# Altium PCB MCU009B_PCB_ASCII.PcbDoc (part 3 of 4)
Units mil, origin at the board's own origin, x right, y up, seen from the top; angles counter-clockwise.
Board outline 2657.23 x 2215.46 mil, 10 copper layers (Top Layer, Internal-Plane 2, Mid-Layer 3, Mid-Layer 4, Internal-Plane 5, Internal-Plane 6, Mid-Layer 7, Mid-Layer 8, Internal-Plane 9, Bottom Layer), stack 60.8 mil thick; 232 components, 196 nets, 851 pads, 493 vias.
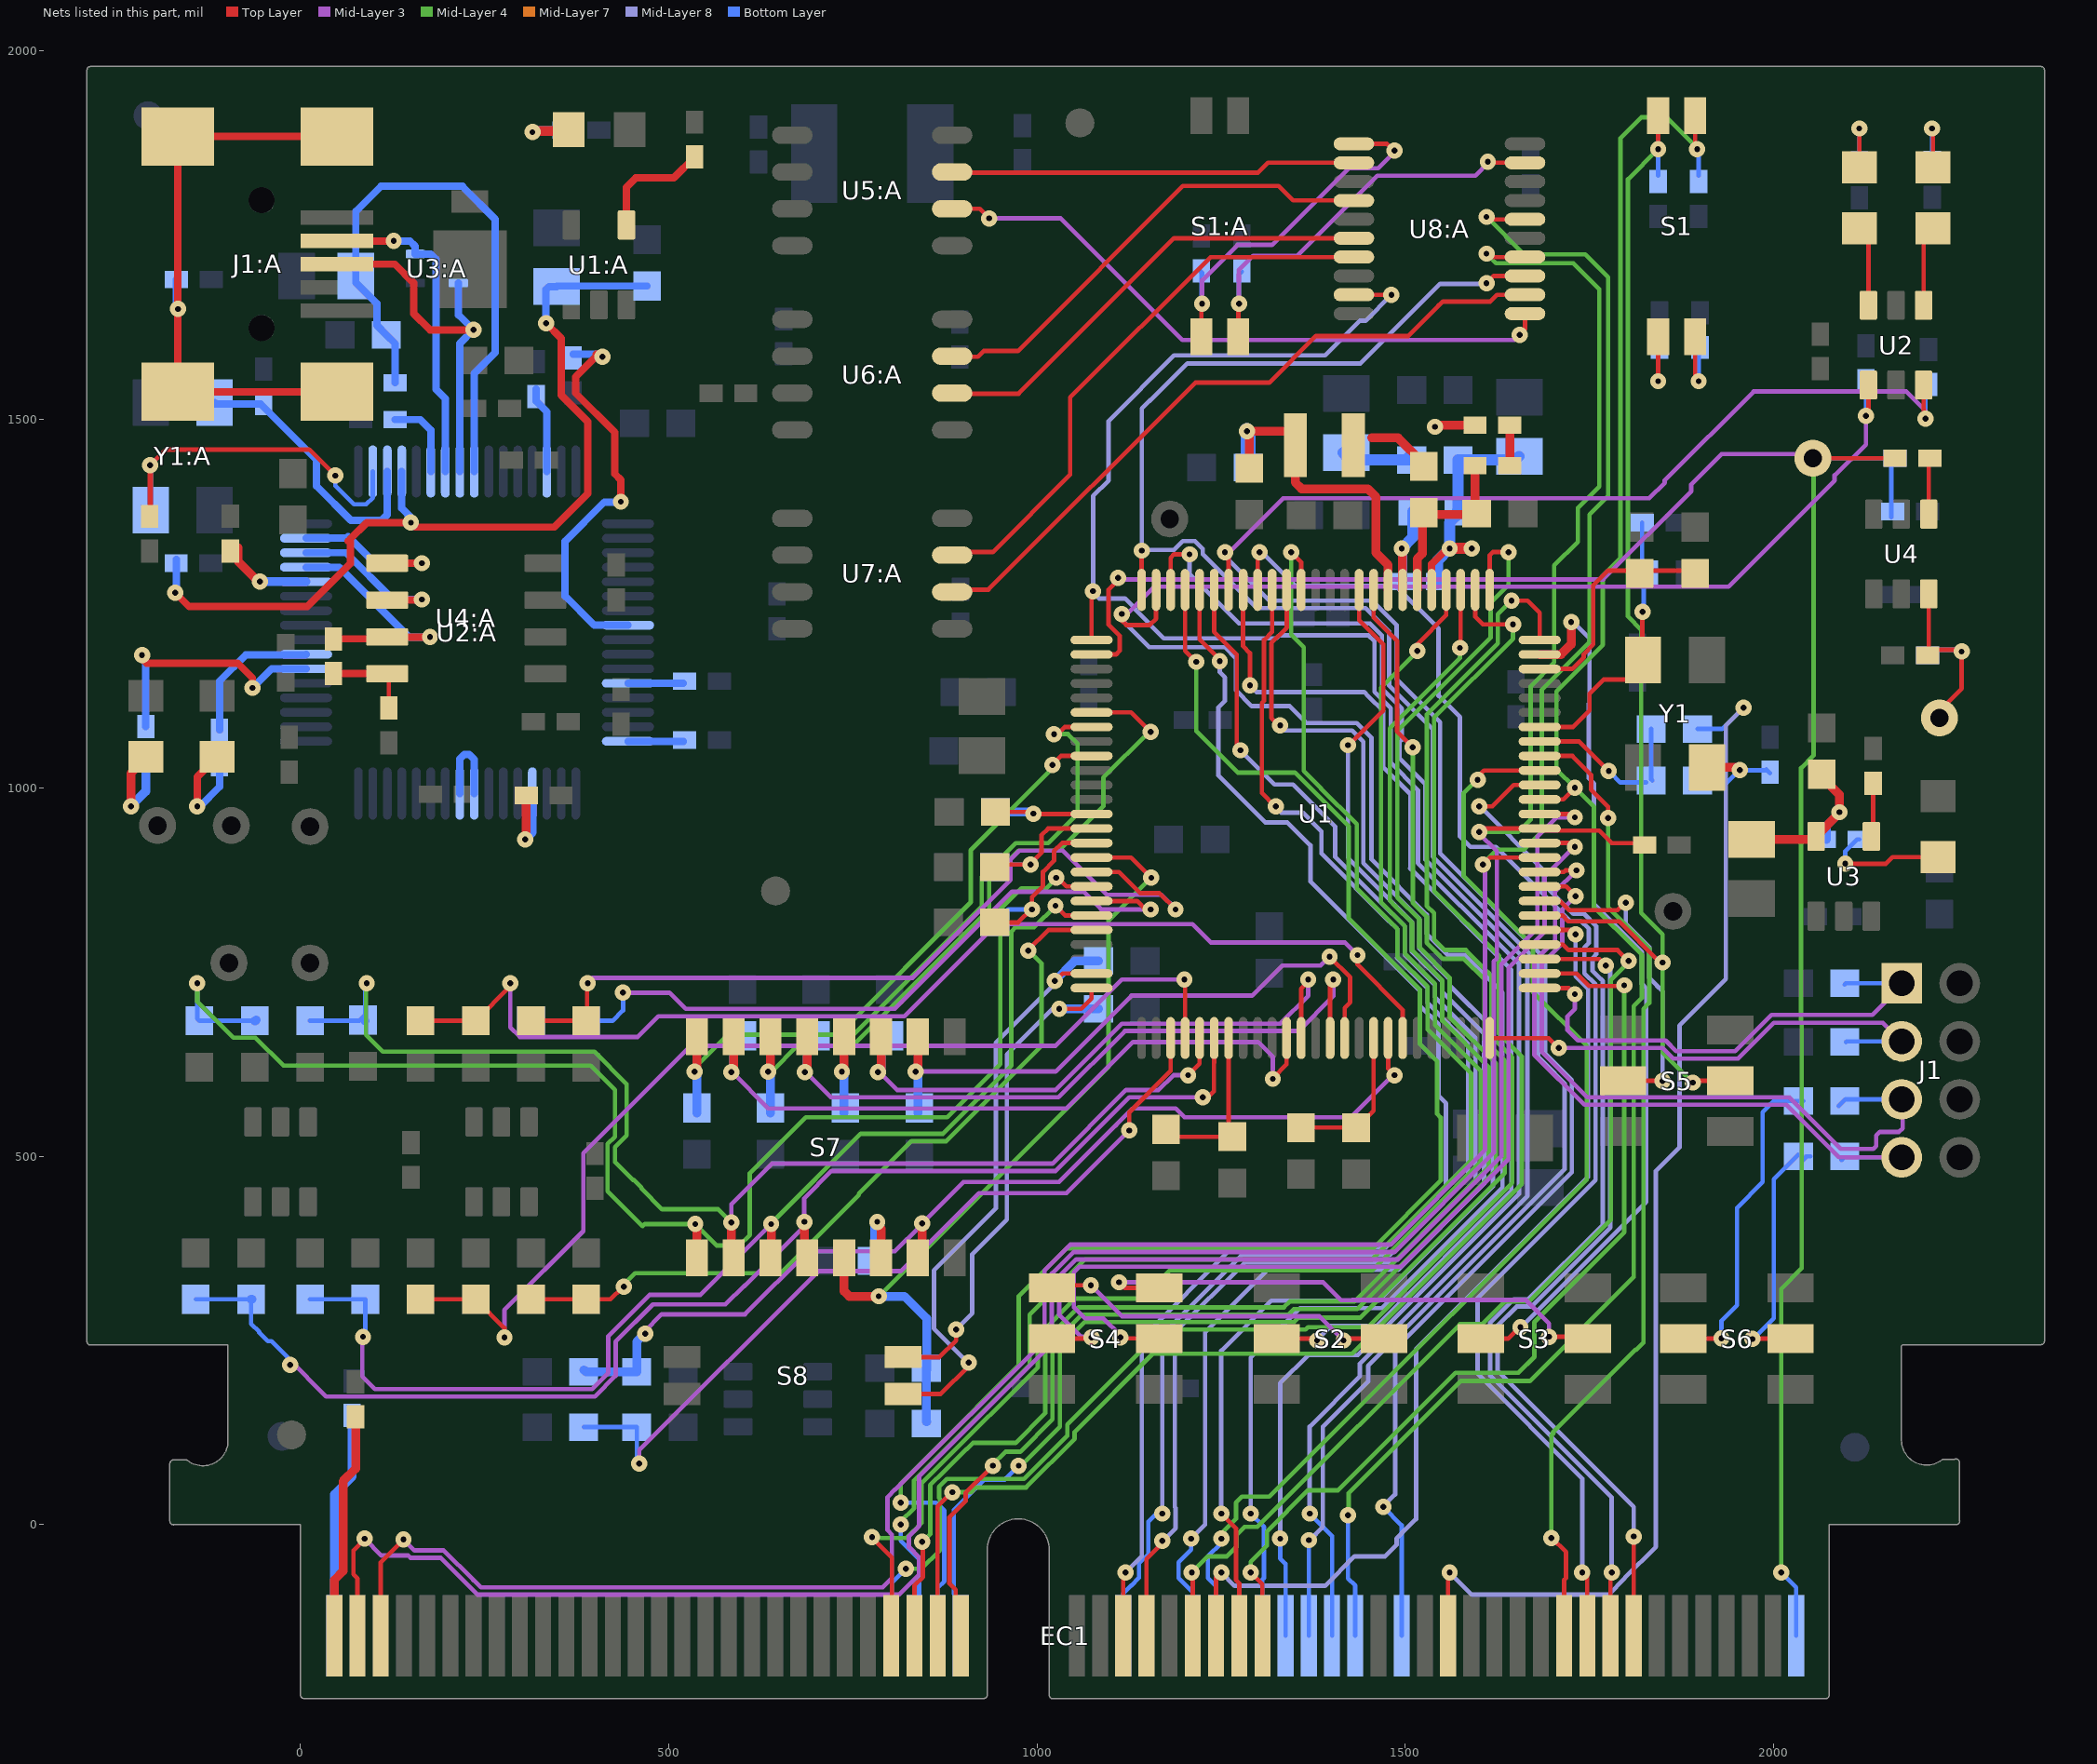
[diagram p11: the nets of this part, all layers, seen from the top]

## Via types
v1: diameter 22, hole 8, Top Layer to Bottom Layer, 414 vias
v2: diameter 22, hole 8, Top Layer to Bottom Layer, tented both sides, 79 vias

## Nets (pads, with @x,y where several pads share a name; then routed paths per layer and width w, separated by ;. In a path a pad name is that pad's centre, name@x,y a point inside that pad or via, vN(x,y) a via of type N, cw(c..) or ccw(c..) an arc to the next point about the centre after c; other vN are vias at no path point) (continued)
MCU_ADC-C0: C55.1 R60.1 U1.19 | length 1040.5
  Top Layer w6: U1.19@1073.97,846.45 1135.55,846.45 v1@1149,833
  Mid-Layer 3 w6: v1(438,722) v1@439,722 ; v1@438,723 v1@439,722 ; v1(1154,835) 1087,835 1063,859 966,859 807,700 523,700 501,722 v1@439,722
  Bottom Layer w6: R60.1@313.1,683.9 C55.1@390.9,683.9 ; C55.1@388.1,683.9 C55.1@390.89,683.9 ; v1(438,722) 438,698 423.9,683.9 C55.1@390.89,683.9
MCU_ADC-C1: C56.1 R61.1 U1.29 | length 1432.9
  Top Layer w6: C56.1@163.1,305.9 R61.1@237.9,305.9 ; R61.1@238.1,305.9 277,267 v1(277,254) v1@277,252 ; v1(1200,740) 1200.93,739.07 U1.29@1200.93,660.43
  Mid-Layer 3 w6: v1(277,254) 277,291.46 384,398.46 384,504 530,650 1025,650 1115,740 v1(1200,740)
MCU_ADC-C2: C57.1 R62.1 U1.21 | length 1073.7
  Top Layer w6: R62.1@313.1,305.9 C57.1@390.9,305.9 ; C57.1@388.1,305.9 420.9,305.9 v1@437,322 ; v1@987.5,779.5 1015.08,807.08 U1.21@1073.97,807.08
  Mid-Layer 4 w6: v1@437,324 454.27,341.27 651.73,341.27 758,447.54 758,449 829.5,520.5 876.64,520.5 1006,649.86 1006,762 v1@988,780
  other v1: 439,323 988,779
MCU_ADC-C4: C58.1 R63.1 U1.17 | length 1187.2
  Top Layer w6: R63.1@313.1,683.9 389.1,683.9 389.1,734.1 v1(390,735) ; U1.17@1073.97,885.82 1111.18,885.82 1140,857 1166,857 v1(1188,835)
  Mid-Layer 3 w6: v1@388,735 395,742 831,742 964,875 964,903 976,915 1035,915 1095,855 1169,855 1188,836 v1(1188,835)
MCU_ADC-C14: C59.1 R64.1 U1.44 | length 1585.8
  Top Layer w6: C59.1@163.1,683.9 R64.1@237.9,683.9 ; R64.1@238.1,683.9 285,730.8 v1(285,735) v1@285,740 ; v1(1435,773) 1435,760 1496.21,698.79 U1.44@1496.21,660.43
  Mid-Layer 3 w6: v1(285,735) 285,675 298,662 458,662 486,690 820,690 945,815 1211,815 1236,790 1418,790 v1(1435,773) v1@1436,772
MCU_ADC-PGA1: C41.2 R37.2 S7.1 U1.18 | length 2040.2
  Top Layer w6: v1(1026,878) 1028,878 1039.86,866.14 U1.18@1073.97,866.14
  Top Layer w12: v1(536,408) 538.1,405.9 S7.1@538.1,362.4
  Mid-Layer 4 w6: v1@-140,740 v1(-140,735) -140,710 -91,661 -61,661 -23,623 394,623 427,590 427,526.6 417,516.6 417,452.54 464.54,405 467.54,408 v1(536,408) 565,379 596,379 610,393 610,477 686,553 878,553 950,625 950,835 978.5,863.5 1012.5,863.5 1026,877 v1(1026,878)
  Bottom Layer w6: v1(-140,735) -140,686.99 C41.2@-136.9,683.9 -62.1,683.9 R37.2@-61,685
  Bottom Layer w12: R37.2@-61.9,683.9 -61.1,683.9 R37.2@-60,685
MCU_ADC-PGA1OF: C34.2 S7.16 U1.9 | length 877.1
  Top Layer w6: v1(1021,1031) 1021,1032 1032.3,1043.3 U1.9@1073.97,1043.3
  Top Layer w12: v1(535,615) 538.1,618.1 S7.16@538.1,662.4
  Mid-Layer 4 w6: v1@530,615 580,665 730,665 910,845 910,915.46 1025.54,1031 v1(1021,1031)
  Bottom Layer w12: C34.2@538.1,558.89 C34.2@538.1,565.5 v1@538.1,615
MCU_ADC-PGA2: C42.2 R39.2 S7.2 U1.30 | length 1707.2
  Top Layer w6: v1(1205,610) 1220.62,625.62 U1.30@1220.62,660.43
  Top Layer w12: v1(585,410) 585,365 S7.2@590,360
  Mid-Layer 3 w6: v1(585,410) 585,435 640,490 1020.86,490 1120.86,590 1165,590 1185,610 v1(1205,610)
  Mid-Layer 4 w6: v1@90,736 89,735 89,665 112,642 399,642 443,598 443,528.46 427,512.46 427,492 451,468 452.46,468 463,457.46 463,456 491,428 567,428 v1(585,410)
  Bottom Layer w6: R39.2@13.1,683.9 79.9,683.9 88,692 88,733 v1(90,735)
MCU_ADC-PGA2OF: C35.2 S7.15 U1.36 | length 986.9
  Top Layer w6: v1(1320,605) 1320,606 1338.73,624.73 U1.36@1338.73,660.43
  Top Layer w12: v1(585,614) 588.1,617.1 S7.15@588.1,662.4
  Mid-Layer 3 w6: v1(585,614) 586,614 635,565 1040,565 1130,655 1300,655 1320,635 v1(1320,605)
  Bottom Layer w12: v1(585,614) 588.1,617.1 C35.2@588.1,655.91
MCU_ADC-PGA3: C43.2 R40.2 S7.3 U1.20 | length 1628.3
  Top Layer w6: v1@1027.5,837.5 1038.23,826.77 U1.20@1073.97,826.77
  Top Layer w12: v1@635,408.8 635.8,408 v1(639,408) 639,369 635,365 S7.3@640,365
  Mid-Layer 3 w6: v1@84,257 84,201 101,184 395.86,184 418,206.14 418,255.86 474.14,312 543,312 v1@633,402
  Mid-Layer 4 w6: v1(639,408) 639,409 760.5,530.5 872.5,530.5 965,623 965,805 971,811 996,811 v1(1025,840)
  Bottom Layer w6: R40.2@13.1,305.9 C43.2@87.1,305.9 ; v1@88.1,260.1 C43.2@88.1,305.9
  other v1: 85,255
MCU_ADC-PGA3OF: C36.2 S7.14 U1.7 | length 886.8
  Top Layer w6: v1(1023,1073) 1028,1073 1037.67,1082.67 U1.7@1073.97,1082.67
  Top Layer w12: v1(635,615) 638.1,618.1 S7.14@638.1,662.4
  Mid-Layer 4 w6: v1@630,615 v1(635,615) 640,615 675,650 735.86,650 925,839.14 925,879.14 970.86,925 1015,925 1055,965 1055,1060 1042,1073 v1(1023,1073)
  Bottom Layer w12: v1(635,615) 638.1,611.9 C36.2@638.1,565.5 C36.2@638.1,558.89
MCU_ADC-PGA4: C44.2 R42.2 S7.4 U1.31 | length 1796.4
  Top Layer w6: v1(1225,580) 1232,580 1240,588 1240,626.39 1240.3,626.7 U1.31@1240.3,660.43
  Top Layer w12: v1(684,411) 684,371 S7.4@690,365
  Mid-Layer 3 w6: v1@-16,225 35,174 400,174 428,202 428,248.46 478.54,299 577,299 603,325 ; 602,323 v1@681,402 ; v1(684,411) 684,443 721,480 1025,480 1125,580 v1(1225,580)
  Bottom Layer w6: C44.2@-141.9,305.9 R42.2@-70.9,305.9 ; R42.2@-66.9,305.9 -66.9,272.68 -55.73,261.51 -55.73,260.73 -44,249 -39,249 -14,224 v1(-14,217)
  Bottom Layer w12: R42.2@-66.9,305.9 R42.2@-65.9,305.9
MCU_ADC-PGA4OF: C37.2 S7.13 U1.39 | length 985.9
  Top Layer w6: U1.39@1397.79,660.43 1397.79,737.21 1400.57,740 v1(1402,740)
  Top Layer w12: v1(685,614) 688.1,617.1 S7.13@688.1,662.4
  Mid-Layer 3 w6: v1(685,614) 686,614 720,580 1029.14,580 1119.14,670 1355,670 1402,717 v1(1402,740)
  Bottom Layer w12: v1(685,614) 688.1,617.1 C37.2@688.1,655.91
MCU_ADC-PGA5: C45.2 R43.2 S7.5 U1.16 | length 1131.2
  Top Layer w6: U1.16@1073.97,905.51 1127.49,905.51 v1(1155,878) v1@1156,877
  Top Layer w12: S7.5@738.1,362.4 738.1,316.9 745,310 v1(785,310)
  Mid-Layer 4 w6: v1(785,310) 1097,622 1097,820 v1(1155,878)
  Bottom Layer w12: v1(785,310) 820,310 850,280 R43.2@850,210 ; R43.2@849.6,212.4 849.59,139.59 C45.2@850,140
MCU_ADC-PGA5OF: C38.2 S7.12 U1.6 | length 865.1
  Top Layer w6: U1.6@1073.97,1102.36 1127.64,1102.36 v1(1154,1076) v1@1155,1075
  Top Layer w12: v1(735,615) 738.1,618.1 S7.12@738.1,662.4
  Mid-Layer 4 w6: v1(735,615) 735,635 935,835 935,875 975,915 1030,915 1090,975 1090,1014 1152,1076 v1(1154,1076)
  Bottom Layer w12: C38.2@738.1,558.89 v1@738.1,615
MCU_ADC-PGA6: C46.2 R45.2 U1.28 | length 1131.5
  Top Layer w6: v1(1125,535) 1125,559.54 1181.25,615.79 U1.28@1181.25,660.43
  Mid-Layer 3 w6: v1@460,85 460,101 703,344 815,344 921,450 1040,450 v1(1125,535)
  Bottom Layer w6: C46.2@384.6,132.4 419.6,132.4 ; 420.4,132.4 R45.2@456.6,132.4 456.6,86.4 v1(460,83)
MCU_ADC-PGA6OF: C39.2 S7.11 U1.37 | length 846.9
  Top Layer w6: U1.37@1358.41,660.43 1358.41,727.41 v1@1370,739
  Top Layer w12: v1(784,614) 788.1,618.1 S7.11@788.1,662.4
  Mid-Layer 3 w6: v1(784,614) 785,615 810,590 1025,590 1115,680 1330,680 1368,718 v1(1368,740)
  Bottom Layer w12: v1(784,614) 788.1,618.1 C39.2@788.1,655.91
MCU_ADC-PGA7: C47.2 R46.2 S7.7 U1.43 | length 1402.7
  Top Layer w6: 1476.53,618.47 U1.43@1476.53,660.43
  Top Layer w12: S7.7@838.1,362.4 844,368.3 v1(844,409)
  Mid-Layer 3 w6: v1@467,262 490.5,285.5 603.5,285.5 689,371 807,371 842,406 v1@841,406 ; v1(844,409) v1@841,406 ; v1@1487,614 1426,553 1200,553 1188,565 1129.54,565 1107,542.46 1107,542 1030,465 900,465 v1@841,406
  Bottom Layer w12: C47.2@385,210 387.6,207.4 R46.2@456.6,207.4 456.6,248.4 467.21,259 v1(468,259)
  other v1: 1485,610
MCU_ADC-PGA7OF: C40.2 S7.10 U1.40 | length 856.6
  Top Layer w6: v1@1395,773 v1(1397,771) 1425,743 1425,709 1417.47,701.47 U1.40@1417.47,660.43
  Top Layer w12: v1(835,615) 838.1,618.1 S7.10@838.1,662.4
  Mid-Layer 3 w6: v1(835,615) 1025,615 1128,718 1292,718 1333,759 1385,759 v1@1394,768
  Bottom Layer w12: v1(835,615) 838.1,611.9 C40.2@838.1,558.89
MCU_GPIO-00: EC1.49 U1.79 | length 2109
  Top Layer w6: v1@775,-17 803,-45 803,-149.64 EC1.49@801.97,-150.67 ; v1@1516,1185 v1(1516,1186) 1516,1195 1555.27,1234.27 U1.79@1555.27,1268.7
  Mid-Layer 4 w6: v1@776,-16 778,-18 822.46,-18 831.73,-8.73 ; 832,-9 843,2 843,55.74 869.26,82 ; 869.28,82 1001,213.72 1001,256 1052,307 1142,307 1180,345 1455,345 1602,492 1602,616 1540,678 1540,734.28 1499,775.28 1499,812.6 1467,844.6 1467,1136 v1@1516,1185
  other v1: 776,-17
MCU_GPIO-01: EC1.51 U1.78 | length 2089
  Top Layer w6: EC1.51@833.46,-150.67 833.46,-82.54 845,-71 v1@845,-24 ; v1(1574,1190) 1574.95,1190.95 U1.78@1574.95,1268.7
  Mid-Layer 4 w6: v1@844.5,-23.5 855,-13 855,53.6 873.4,72 ; 873.43,72 903.71,102.29 ; 904,102 913,111 971,111 1011,151 1011,249.74 1056.26,295 1335,295 1343,303 1431,303 1613,485 1613,621 1550,684 1550,738.43 1509,779.43 1509,816.74 1486.74,839 1486.74,839.26 1479,847 1479,1081.14 1574,1176.14 v1(1574,1190) v1@1576,1192
  other v1: 844,-23
MCU_GPIO-02: EC1.53 U1.77 | length 2103
  Top Layer w6: EC1.53@864.96,-150.67 864.96,24.96 v1@885,45 ; U1.77@1594.64,1268.7 1594.64,1232.36 1605,1222 v1(1646,1222) v1@1648,1222
  Mid-Layer 4 w6: v1(885,44) 910,44 916.52,50.52 985.12,50.52 1051,116.4 1051,126 1157,232 1427.46,232 1658,462.54 1658,635.28 1627,666.28 1627,772 1539,860 1539,1095.46 1646,1202.46 v1(1646,1222)
MCU_GPIO-03: EC1.55 U1.76 | length 2166.3
  Top Layer w6: EC1.55@889.32,-116 889.32,-88.32 881,-80 881,10 903,32 903,43 v1(940,80) ; U1.76@1614.32,1268.7 1614.32,1315.68 1618.64,1320 v1(1640,1320)
  Mid-Layer 4 w6: v1@939,81 957,99 977,99 1021,143 1021,245.6 1060.4,285 1341,285 1348.5,292.5 1434.64,292.5 1623,480.86 1623,626 1560,689 1560,742.57 1519,783.57 1519,821.14 1489,851.14 1489,1077 1615.5,1203.5 1615.5,1250.96 1640,1275.46 v1(1640,1320) ; v1(940,80) v1@940,81
MCU_GPIO-04: EC1.50 U1.75 | length 2184.7
  Top Layer w6: v1(1644,1254) 1666,1254 1682.23,1237.77 U1.75@1682.23,1200.78
  Mid-Layer 4 w6: v1(822,-60) 843,-60 868,-35 868,35.54 867,36.54 867,51.46 877.54,62 982.46,62 1041,120.54 1041,136 1170,265 1364.54,265 1367.54,268 1449.31,268 1645,463.69 1645,634.14 1617,662.14 1617,744.6 1612.8,748.8 ; 1613,749 1582,780 1553.14,780 1539,794.14 1539,830 1529,840 1529,1099.6 1625.5,1196.1 1625.5,1235.5 v1(1644,1254)
  Bottom Layer w6: EC1.50@801.97,-150.67 803,-149.64 803,-79 v1(822,-60)
MCU_GPIO-05: EC1.52 U1.89 | length 2190.7
  Top Layer w6: v1(1345,1320) 1358.41,1306.59 U1.89@1358.41,1268.7
  Mid-Layer 4 w6: v1(815,0) 815,4.54 833,22.54 833,59.88 865.12,92 ; 865.14,92 990,216.86 990,285 1065,360 1455,360 1589,494 1589,613 1530,672 1530,730.14 1489,771.14 1489,808.46 1434,863.46 1434,950.6 1385,999.6 1385,1000 1362,1023 1362,1191 1345,1208 v1(1345,1320)
  Bottom Layer w6: v1(815,0) 815,-22 840,-47 840,-144.13 EC1.52@833.46,-150.67
MCU_GPIO-06: EC1.54 U1.97 | length 2213.7
  Top Layer w6: U1.97@1200.93,1268.7 1200.93,1186.07 v1(1216,1171)
  Mid-Layer 4 w6: v1(815,30) 815,56.02 860.98,102 975,216 975,310 1040,375 1455.86,375 1548,467.14 1548,552.46 1543,557.46 1543,629 1519.7,652.3 1519.7,726.3 1464,782 1463.54,782 1423,822.54 1423,947.46 1349.73,1020.73 1272.27,1020.73 1216,1077 v1@1216,1170 ; v1@1215,1171 v1@1216,1170 ; v1(1216,1171) v1@1216,1170
  Bottom Layer w6: v1(815,30) 863,30 874,19 874,-77 864.96,-86.04 EC1.54@864.96,-150.67
MCU_GPIO-07: EC1.56 U1.84 | length 2014.8
  Top Layer w6: U1.84@1456.84,1268.7 1456.84,1231.16 1488.5,1199.5 1488.5,1076.5 v1(1510,1055)
  Mid-Layer 4 w6: v1@976,78 1031,133 1031,241.46 1064.54,275 1349,275 1355,281 1439,281 1635,477 1635,630 1607,658 1607,740.46 1579.46,768 1551,768 1529,790 1529,825.28 1510,844.28 v1(1510,1055)
  Bottom Layer w6: EC1.56@889.32,-111 889.32,-96.32 887,-94 887,20 928,61 956,61 v1(975,80)
MCU_GPIO-08: S3.5 U1.74 | length 1209.5
  Top Layer w6: S3.5@1602.17,252.4 1639.4,252.4 v1@1656,269
  Top Layer w12: U1.74@1682.23,1181.1 1711.1,1181.1 1725,1195 v1(1725,1225)
  Mid-Layer 8 w6: v1(1656,268) 1657,268 1827,438 1827,728 1821,734 1821,777 1756,842 1756,1006 1749,1013 1749,1114.54 1750,1115.54 1750,1203 v1@1728,1225
MCU_GPIO-09: EC1.71 U1.90 | length 1854.2
  Top Layer w6: v1(1250,15) 1270,-5 1270,-75 1274.41,-79.41 EC1.71@1274.41,-150.67 ; v1@1329,1084 1318,1095 1318,1196.46 1339,1217.46 1339,1268.43 U1.90@1338.73,1268.7
  Mid-Layer 8 w6: v1(1250,15) 1250,236 1318,304 1463.86,304 1618.71,458.86 1618.71,673.29 1560,732 1560,740.57 1519,781.57 1519,822 1443,898 1443,1062.46 1427.46,1078 1336,1078 v1@1330,1084
  other v1: 1330,1085
MCU_GPIO-10: S2.2 U1.93 | length 1453.3
  Top Layer w6: U1.93@1279.67,1268.7 1279.67,1192.33 1289,1183 v1@1289,1145 ; S2.2@1325.27,252.4 1377.6,252.4 v1(1380,250)
  Mid-Layer 8 w6: v1(1289,1139) 1298,1130 1444,1130 1450,1124 ; v1(1380,250) 1379,250 1399,270 1461,270 1643.86,452.86 1643.86,753.14 1507,890 ; 1450.07,1124.07 1470,1104.14 1470,1028 1507,991 1507,890 ; 1506,891 1507,890
MCU_GPIO-11: EC1.73 U1.52 | length 1300.4
  Top Layer w6: v1(1290,-65) 1305.9,-80.9 EC1.73@1305.9,-150.67 ; U1.52@1682.23,748.03 1731.97,748.03 1749,731 1798,731 v1@1801,734
  Mid-Layer 4 w6: v1(1290,-65) 1290,-50.46 1312,-28.46 1312,-9 1367.73,46.73 1408.73,46.73 1568,206 1653.46,206 1675,227.54 1675,275 1797,397 v1(1797,732)
MCU_GPIO-12: J1.1 R3.2 U1.51 | length 688.4
  Top Layer w6: U1.51@1682.23,728.34 1721.66,728.34 v1(1730,720)
  Mid-Layer 3 w6: v1(1730,720) 1730,700 1720,690 1720,671 1734,657 1853.14,657 1867.64,642.5 1947.5,642.5 1997,692 2134,692 J1.1@2176,734
  Bottom Layer w6: R3.2@2096,733 2097.75,734.75 J1.1@2173.62,734.75
MCU_GPIO-13: J1.3 R4.2 U1.50 | length 690.4
  Top Layer w6: U1.50@1614.32,660.43 1694.57,660.43 v1(1708,647)
  Mid-Layer 3 w6: v1(1708,647) 1849,647 1863.5,632.5 1951.64,632.5 2000.14,681 2148,681 J1.3@2174,655 ; J1.3@2181.31,663.69 J1.3@2185,660
  Bottom Layer w6: R4.2@2098,655 2099.01,656.01 J1.3@2173.62,656.01 ; J1.3@2180,655 J1.3@2185,660
MCU_GPIO-14: EC1.61 U1.96 | length 1887.7
  Top Layer w6: EC1.61@1116.93,-150.67 1116.93,-66.93 1118.86,-65 v1(1120,-65) ; U1.96@1220.62,1268.7 1220.62,1201.38 v1@1249,1173
  Mid-Layer 8 w6: v1(1120,-65) 1142,-43 1142,253 1265,376 1473,376 1555,458 1555,572 1545,582 1545,678.98 1520,703.98 1520,724 1371,873 1371,922 1340,953 1310,953 1246,1017 1246,1109 1255,1118 1255,1150 1248,1157 v1(1248,1172) ; v1@1248,1174 v1@1249,1173
MCU_GPIO-15: EC1.63 U1.95 | length 1884.9
  Top Layer w6: EC1.63@1148.42,-150.67 1148.42,-46.58 1170,-25 v1(1170,-22) ; U1.95@1240.3,1268.7 1240.3,1211.7 1271,1181 1271,1056 v1(1276,1051)
  Mid-Layer 8 w6: v1@1171,-22 1188,-5 1188,22.46 1187,23.46 1187,260.86 1282.14,356 1484,356 1595,467 1595,661 1540,716 1540,732.28 1499,773.28 1499,812.6 1482.6,829 1482,829 1404.5,906.5 1404.5,947.5 1347.5,1004.5 1322.5,1004.5 v1(1276,1051)
MCU_GPIO-16: EC1.67 U1.54 | length 1358.2
  Top Layer w6: v1(1210,-65) 1211.42,-66.42 EC1.67@1211.42,-150.67 ; U1.54@1682.23,787.4 1714,787.4 1721.4,780 1788,780 v1(1803,765) ; v1@1801,763 v1@1804,760
  Mid-Layer 4 w6: v1(1210,-65) 1232,-43 1257.46,-43 1271,-29.46 1271,-13.54 1281.54,-3 1299,-3 1574,272 1604,272 1635,303 1668,303 1779,414 1779,739.46 1803,763.46 v1(1803,765)
MCU_GPIO-17: EC1.69 U1.55 | length 1352
  Top Layer w6: EC1.69@1242.91,-150.67 1242.91,-72.09 v1(1250,-65) ; U1.55@1682.23,807.08 1723.92,807.08 v1@1731,800
  Mid-Layer 8 w6: v1(1250,-65) 1268,-83 1391,-83 1431,-43 1472.46,-43 1488,-27.46 1488,-19 1514.5,7.5 1514.5,238.33 1748,471.83 1748,727.46 1731,744.46 v1(1731,801)
MCU_GPIO-18: R7.2 R16.2 U1.68 | length 240.8
  Top Layer w6: U1.68@1682.23,1062.99 1736.01,1062.99 v1(1776,1023) v1@1780,1019
  Bottom Layer w6: v1@1778,1021 1791.6,1007.4 R16.2@1826.6,1007.4 ; R7.2@1833.5,1080 1833.5,1011.5 R16.2@1835,1010
MCU_GPIO-22: L3.2 R19.1 R22.2 U1.83 | length 477.7
  Top Layer w12: v1@1286,1484 1353,1484 L3.2@1360,1477 ; R22.2@1288.1,1433.9 v1@1288.1,1481.9 ; L3.2@1350.63,1465 1350.63,1414.37 1359,1406 1449,1406 1460,1395 1460,1319 1476.53,1302.47 U1.83@1476.53,1268.7
  Bottom Layer w20: v1(1285,1484) 1285,1485 1286.5,1483.5 R19.1@1286.5,1435
MCU_GPIO-23: R18.1 R21.2 R24.2 U1.81 | length 253.2
  Top Layer w12: U1.81@1515.9,1268.7 1515.9,1307.1 ; R21.2@1515.9,1365.9 R21.2@1517,1364.79 ; 1516,1307 1515.9,1307.1 ; R21.2@1518,1373 R21.2@1520.1,1370.9 ; R24.2@1594.48,1437.4 R18.1@1594.48,1370.52 ; R18.1@1595,1370 R18.1@1594.48,1370.52 ; 1515.9,1307.1 1515.9,1310.9 1523,1318 1523,1368 R21.2@1520.1,1370.9 ; R21.2@1520.1,1370.9 1594.1,1370.9 R18.1@1594.48,1370.52
MCU_GPIO-24: R25.2 S1.2 S5.2 U1.56 | length 1649.9
  Top Layer w6: U1.56@1680,827 U1.56@1682.23,827 ; U1.56@1682.23,826.77 1713.23,826.77 1721,819 1790,819 v1@1843,766 ; S1.2@1843.1,1912.4 v1@1843.1,1869.1 ; v1(1890,600) 1892.4,602.4 S5.2@1940.93,602.4 ; v1(1843,1867) 1843.1,1866.9 v1@1843.1,1869.1 ; v1(1843,1867) 1842,1868 v1@1843,1869 ; v1(1843,1867) v1@1843,1869 ; v1@1843,1869 v1@1843.1,1869.1
  Mid-Layer 4 w6: v1(1843,1867) 1802,1826 1802,1232.54 1820,1214.54 1820,830.25 1849,801.25 v1(1849,763) 1849,641 1889,601 v1@1891,601
  Bottom Layer w6: v1(1843,1867) 1843,1868 1843.1,1868.1 R25.2@1843.1,1831.02
MCU_GPIO-25: S5.5 U1.57 | length 445.3
  Top Layer w6: U1.57@1682.23,846.45 1709.69,846.45 1722,834.14 1722,834 1788,834 v1@1798.5,844.5 ; S5.5@1795.27,602.4 1848.6,602.4 v1(1849,602)
  Mid-Layer 8 w6: v1@1801,846 v1(1799,844) 1799,816 1831,784 1831,742.14 1841.07,732.07 ; 1841,732 1849,724 v1(1849,602)
MCU_GPIO-26: J1.5 R5.2 U1.58 | length 982.8
  Top Layer w6: U1.58@1682.23,866.14 1718.41,866.14 1731,853.54 v1(1731,853)
  Mid-Layer 3 w6: v1(1731,853) 1713,835 1713,789 1685,761 1685,642 1747,580 2021.14,580 2091.14,510 2135,510 2139,514 2139,528 2144.09,533.09 2170.09,533.09 2175,538 2175,571 J1.5@2183,579
  Bottom Layer w6: R5.2@2088,568 2097.27,577.27 J1.5@2173.62,577.27
MCU_GPIO-27: J1.7 R6.2 U1.59 | length 975.9
  Top Layer w6: U1.59@1682.23,885.82 1714.82,885.82 1717,888 v1(1732,888)
  Mid-Layer 3 w6: v1(1732,888) 1703,859 1703,793.14 1675,765.14 1675,637.86 1742.86,570 2017,570 2088.47,498.53 J1.7@2173.62,498.53 ; J1.7@2180,500 2185,495 J1.7@2190,495
  Bottom Layer w6: R6.2@2092,495 2095.53,498.53 J1.7@2173.62,498.53
MCU_GPIO-28: EC1.76 U1.1 U8:A.9 | length 2838.4
  Top Layer w6: U1.1@1073.97,1200.78 v1@1073.97,1265.97 ; U8:A.9@1430.05,1669.27 v1@1479.27,1669.27 ; v1(1481,1669) 1479.55,1669 v1@1479.27,1669.27 ; v1@1483,1670 1482.27,1669.27 v1@1479.27,1669.27
  Mid-Layer 8 w6: v1@1075,1266 1084,1257 1119.46,1257 1133,1243.46 1133,1242 1172,1203 1324.54,1203 1328.54,1207 1450,1207 1458,1199 1458,1130.28 1480,1108.28 1480,1034 1517,997 1517,898 1575,840 1575.43,840 1654,761.43 1654,448.54 1435.46,230 1368,230 1330,192 v1(1330,-19) ; v1@1076,1266 v1(1076,1267) 1076,1396 1097,1417 1097,1498 1186,1587 1391,1587 1438,1634 1446,1634 v1(1481,1669)
  Bottom Layer w6: v1(1330,-19) 1330,-46 1337,-53 ; EC1.76@1337.4,-150.67 1337.4,-53
MCU_GPIO-29: EC1.78 U1.100 U8:A.13 | length 2843.5
  Top Layer w6: U1.100@1141.88,1268.7 v1@1141.88,1322 ; v1(1610,1685) 1619.87,1694.87 U8:A.13@1662.34,1694.87
  Mid-Layer 8 w6: v1@1141,1323 v1(1142,1322) 1142,1515 1153,1526 ; v1@1143,1323 1186,1323 1198,1335 1214.46,1335 1225,1324.46 1225,1317 1298,1244 1446,1244 1478,1212 1478,1138.57 1537,1079.57 1537,906.72 1680,763.72 1680,635.4 1691.2,624.2 ; 1153.5,1525.5 1204,1576 1439,1576 1547,1684 v1@1611,1684 ; v1(1369,-21) 1370,-21 1388,-3 1388,133 1449.37,194.37 1449.37,215.63 1716,482.26 1716,599 1691,624 ; v1@1608,1687 v1@1610,1689
  Bottom Layer w6: EC1.78@1368.9,-150.67 1368.9,-24.1 v1@1369,-24
MCU_GPIO-30: EC1.80 U1.98 | length 1970.7
  Top Layer w6: U1.98@1181.25,1268.7 1181.25,1312.25 1186,1317 v1(1207,1317)
  Mid-Layer 8 w6: v1(1207,1317) 1207,1290 1274,1223 1452,1223 1468,1207 1468,1134.43 1495,1107.43 1495,1065.46 1492,1062.46 1492,1040 1527,1005 1527,902.57 1665.63,763.94 1665.63,446.03 1438,218.4 1438,201 1370,133 v1(1370,15)
  Bottom Layer w6: v1(1370,15) 1400.39,-15.39 EC1.80@1400.39,-150.67
MCU_GPIO-31: EC1.74 R12.1 U1.99 U2.1 | length 3290.4
  Top Layer w6: v1@1115,1227 1121,1221 1153,1221 1161.56,1229.56 U1.99@1161.56,1268.7 ; v1(2125,1505) 2128.5,1508.5 U2.1@2128.5,1546.73
  Mid-Layer 3 w6: v1(1115,1236) 1122,1236 1159,1273 1938.46,1273 2082.5,1417.04 2082.5,1424.5 ; 2083,1424 2125,1466 v1(2125,1505)
  Mid-Layer 8 w6: v1(1115,1236) 1115,1228 1152,1191 1255,1191 1270,1176 1270,1132.54 1291.54,1111 1343,1111 1366,1088 1434,1088 1454,1068 1454,903 1529,828 1529,802 1558,773 1580.86,773 1631.78,722.07 1631.78,457.78 1468,294 1357,294 1290,227 v1(1290,15)
  Bottom Layer w6: v1(1290,15) 1308,-3 1308,-72.46 1305.9,-74.55 EC1.74@1305.9,-150.67 ; v1(2125,1505) R12.1@2125,1552.76
MCU_GPIO-32: EC1.82 R26.1 S1.1 U1.64 | length 2629.3
  Top Layer w6: U1.64@1682.23,984.25 1714.25,984.25 v1(1730,1000) ; S1.1@1893.1,1912.4 1893.1,1866.9 1894,1866 1896,1868 v1(1896,1867)
  Mid-Layer 4 w6: v1@1423,12 1423,43 1575,195 1669,195 1810,336 1810,704 1821,715 1821,773.46 1784.46,810 1783.86,810 1765,828.86 1765,829 1756,838 1756,974 v1(1730,1000) 1705,1025 1705,1131 1768,1194 1768,1288 1792,1312 1792,1882 1820,1910 1855,1910 1896,1869 v1(1896,1867) 1898,1867 v1@1900,1865
  Bottom Layer w6: v1(1422,13) 1422,-73 1431.89,-82.89 EC1.82@1431.89,-150.67 ; v1(1896,1867) 1896,1870 1898.1,1867.9 R26.1@1898.1,1831.02
MCU_GPIO-33: EC1.105 U1.53 | length 1156.2
  Top Layer w6: U1.53@1682.23,767.71 1763.29,767.71 v1(1772,759) ; EC1.105@1809.84,-150.67 1809.84,-84.84 1810,-84.68 v1(1810,-16)
  Mid-Layer 8 w6: v1@1772,758 1778,752 1778,403.14 1670.86,296 1651,296 1625,270 1625,209 1810,24 v1(1810,-16)
MCU_GPIO-34: EC1.86 R13.1 U1.94 U2.3 | length 3059.2
  Top Layer w6: v1(1255,1320) 1259.99,1315.01 U1.94@1259.99,1268.7 ; 2203.31,1511.69 U2.3@2203.31,1546.73
  Mid-Layer 3 w6: v1(1255,1320) 1261,1320 1334,1393 1831,1393 1852,1414 1852,1417.46 1972.54,1538 2180,1538 2206,1512
  Mid-Layer 8 w6: v1@1251,1320 1251,1318.54 1315.54,1254 1455,1254 1488,1221 1488,1148 1547,1089 1547,910.86 1690,767.86 1690,639.54 1726,603.54 1726,478.12 1486,238.12 1486,41 v1@1469,24
  Bottom Layer w6: v1(1470,24) 1494.88,-0.88 EC1.86@1494.88,-150.67 ; R13.1@2205,1551.38 2206,1550.38 v1(2206,1501)
MCU_GPIO-35: S4.2 U1.63 | length 1391.7
  Top Layer w6: S4.2@1020.27,252.4 1072.4,252.4 v1(1074,254) ; U1.63@1682.23,964.56 1725.44,964.56 v1(1730,960)
  Mid-Layer 3 w6: v1@1065,255 1060,255 1030,285 1030,336.72 1053.28,360 1490,360 1630,500 1630,760.14 1679,809.14 1679,934 1705,960 v1(1730,960)
  Mid-Layer 7 w6: v1@1072,256 1071,255 1072,254 v1(1074,254)
MCU_GPIO-37: S4.5 U1.61 | length 1341
  Top Layer w6: v1(1113,254) 1114,253 1165.33,253 S4.5@1165.93,252.4 ; U1.61@1682.23,925.19 v1@1724.81,925.19
  Mid-Layer 3 w6: v1(1113,254) 1113,257 1090,280 1065,280 1050,295 1050,342.57 1057.43,350 1494.14,350 1640,495.86 1640,756 1689,805 1689,880 1729,920 v1(1730,920)
MCU_GPIO-39: EC1.62 U1.91 | length 1875.5
  Top Layer w6: U1.91@1319.04,1268.7 U1.91@1319.04,1268.7 1319,1211.6 1308,1200.6 1308,1118 1305,1115 1305,993 v1@1323,975
  Mid-Layer 8 w6: v1(1170,15) 1170,258 1278,366 1479,366 1585,472 1585,653 1558,680 ; v1@1323,975 1331.5,966.5 1360.5,966.5 1386,941 1386,910.86 1477.86,819 1478.46,819 1489,808.46 1489,770 1488.57,769.57 1530,728.14 1530,708.12 1558.06,680.06
  Bottom Layer w6: EC1.62@1116.93,-150.67 1116.93,-93.07 1127,-83 1127.46,-83 1138.42,-72.03 1138.42,-52.58 1151,-40 1151,4.15 1161.85,15 v1(1170,15)
  other v1: 1324,975
MCU_GPIO-40: EC1.68 U1.85 | length 1820.1
  Top Layer w6: v1@1421,1056 1470,1105 1470,1195 1437.16,1227.84 U1.85@1437.16,1268.7
  Mid-Layer 8 w6: v1(1209,-19) 1228,0 1228,261 1313,346 1490,346 1606.64,462.64 1606.64,666.36 1550,723 1550,736.43 1509,777.43 1509,817.86 1422,904.86 v1(1422,1058) 1422,1060 v1@1420,1062
  Bottom Layer w6: v1(1209,-19) 1209,-34 1192,-51 1192,-72.46 1211.42,-91.87 EC1.68@1211.42,-150.67
MCU_GPIO-56: EC1.103 U1.65 | length 1448.5
  Top Layer w6: v1(1600,975) 1618,975 1646.93,1003.93 U1.65@1682.23,1003.93 ; EC1.103@1778.35,-150.67 1778.35,-66.65 v1(1780,-65)
  Mid-Layer 8 w6: v1@1599,975 v1(1600,975) ; v1@1600,976 1688,888 1688,869 1728,829 1742.6,829 1759,812.6 1759,774 1754,769 1754,751.54 1764.54,741 1765,741 1768,738 1768,407.28 1666.72,306 1646.86,306 1615,274.14 1615,202 1780,37 v1(1780,-65)
MCU_GPIO-57: EC1.70 U1.66 | length 1578.5
  Top Layer w6: v1@1597,1014 1606.62,1023.62 U1.66@1682.23,1023.62
  Mid-Layer 4 w6: v1(1250,-19) 1243,-19 1270,8 1270,30 1278,38 1315,38 1562,285 1563,285 1746,468 1746,650 1673,723 1673,786 1579,880 1579,993 v1@1598,1012
  Bottom Layer w6: EC1.70@1242.91,-150.67 1242.91,-83.37 1232,-72.46 1232,-43 1250,-25 v1(1250,-19)
  other v1: 1598,1011
MCU_GPIO-58: EC1.99 U1.67 | length 1355.5
  Top Layer w6: U1.67@1682.23,1043.3 1726.7,1043.3 1752,1018 1752,997.54 1775,974.54 v1(1775,959) ; v1(1698,-18) 1699,-18 1718,-37 1718,-72.46 1715.35,-75.1 EC1.99@1715.35,-150.67
  Mid-Layer 4 w6: v1(1698,-18) 1698,121 1701,124 1700,125 1812.5,237.5 ; v1@1775,961 v1(1775,959) v1@1775,957 ; v1@1779,961 v1@1775,957 ; 1813,237 1823,247 1823,700 1831,708 1831,782 1775,838 v1@1775,957
MCU_GPIO-59: EC1.101 U1.92 | length 1967.2
  Top Layer w6: U1.92@1299.36,1268.7 1299.36,1320.36 1302,1323 v1(1302,1320) ; v1(1740,-65) 1745,-65 1746.85,-66.85 EC1.101@1746.85,-150.67
  Mid-Layer 8 w6: v1@1302,1323 v1(1302,1320) 1305,1320 1351,1274 1487,1274 1545,1216 1545,1125 1574,1096 1574,934 1588,920 1622.86,920 1723.86,819 1738.46,819 1749,808.46 1749,789.54 1743,783.54 1743,748.4 1758,733.4 1758,467.69 1598,307.69 1598,204.86 1740,62.86 v1(1740,-65)
MCU_TCK: EC1.5 U1.60 U8:A.16 | length 3628.2
  Top Layer w6: EC1.5@109.05,-150.67 109.05,-50.95 v1(140,-20) v1@141,-19 ; v1(1605,896) 1614.51,905.51 U1.60@1682.23,905.51 ; v1(1610,1775) 1613.36,1771.64 U8:A.16@1662.34,1771.64
  Mid-Layer 3 w6: v1(140,-20) 155,-35 194.6,-35 234.8,-75.2 ; 235,-75 245,-85 790.46,-85 803,-72.46 803,-13.46 797,-7.46 797,37.46 807.54,48 808,48 1010,250 1010,345 1045,380 1480,380 1608,508 1608,897 1607,896 v1(1605,896)
  Mid-Layer 4 w6: v1@1605,897 1624,916 1661,916 1685,940 1685,1133 1750,1198 1750,1371 1775,1396 1775,1693 1744,1724 1661,1724 v1(1610,1775)
MCU_TMS: EC1.3 R31.1 U1.62 U8:A.14 | length 3847.2
  Top Layer w6: EC1.3@77.56,-150.67 77.56,-73.01 72,-67.46 72,-35 v1@88,-19 ; v1@1597,937 v1(1600,940) 1604.88,944.88 U1.62@1682.23,944.88 1685.11,942 1763,942 1780,925 1820,925 R31.1@1825,920 ; v1(1610,1725) 1614.54,1720.46 U8:A.14@1662.34,1720.46
  Mid-Layer 3 w6: v1(87,-19) 110,-42 146.46,-42 149.46,-45 190.46,-45 240.46,-95 812.46,-95 840,-67.46 840,-44.46 826,-30.46 826,-15.54 840,-1.54 840,65.86 1020,245.86 1020,340.86 1049.14,370 1485,370 1620,505 1620,764.28 1624,768.28 1624,914 v1@1599,939
  Mid-Layer 4 w6: v1@1602,940 1653,940 1670,957 1670,1138 1702,1170 1702,1302 1734,1334 1734,1380 1763,1409 1763,1677 1728,1712 1623,1712 v1(1610,1725)
MCU_X1: C23.1 R17.2 U1.69 Y1.3 | length 359.4
  Top Layer w6: U1.69@1682.23,1082.67 1727.67,1082.67 1750,1105 1750,1128 1769,1147 Y1.3@1810,1147 ; Y1.3@1821.52,1173.5 1821.52,1238.52 v1(1822,1239)
  Bottom Layer w6: v1@1820,1240 1823.5,1243.5 R17.2@1823.5,1286.5 ; C23.1@1821.38,1360 1821.38,1288.62 R17.2@1823.5,1286.5 ; R17.2@1823.5,1290 R17.2@1823.5,1286.5
MCU_XRSN: C29.2 EC1.120 R27.1 R29.2 TP5.1 U1.2 | length 3103.5
  Top Layer w6: U1.2@1073.97,1181.1 1107.1,1181.1 1112,1186 1112,1206.54 1097,1221.54 1097,1269 v1@1111,1283 ; TP5.1@2055,1450 2057.6,1447.4 R29.2@2164.48,1447.4
  Mid-Layer 3 w6: v1@1108,1286 1111,1283 1768.46,1283 1888,1402.54 1888,1412 1929,1453 TP5.1@2061,1453
  Mid-Layer 4 w6: v1(2010,-65) 2010,320 2038,348 2038,681.54 2037,682.54 2037,1027 2054,1044 TP5.1@2054,1448
  Bottom Layer w6: v1(2010,-65) 2030.31,-85.31 EC1.120@2030.31,-150.67 ; TP5.1@2055,1445 2057.4,1447.4 R27.1@2164.48,1447.4 ; C29.2@2159.48,1367.4 R27.1@2159.48,1444.48
  other v1: 1110,1285
MID_SCI-RX: U5:A.6 U8:A.11 | length 879.8
  Top Layer w6: U5:A.6@883.5,1785.87 922.13,1785.87 v1(935,1773) ; v1(1655,1615) 1662.34,1622.34 U8:A.11@1662.34,1643.68
  Mid-Layer 3 w6: v1(935,1773) 1032,1773 1197,1608 1648,1608 v1(1655,1615)
MID_SCI-TX: U7:A.3 U8:A.7 | length 772.4
  Top Layer w6: U7:A.3@885,1320 940,1320 1045,1425 1045,1530 1235.46,1720.46 U8:A.7@1430.05,1720.46
MID_TCK: U6:A.7 U8:A.4 | length 646.8
  Top Layer w6: U6:A.7@890,1585 919.54,1585 927.54,1593 974,1593 1198,1817 1328,1817 1347.77,1797.23 U8:A.4@1430.05,1797.23
  Top Layer w12: U8:A.4@1428.28,1799 U8:A.4@1430.05,1797.23
MID_TDI: U5:A.7 U8:A.2 | length 554.7
  Top Layer w6: U5:A.7@885,1835 1300,1835 1313.41,1848.41 U8:A.2@1430.05,1848.41
  Top Layer w12: U5:A.7@883.5,1835.87 U5:A.7@886.37,1833
MID_TDO: U7:A.2 U8:A.12 | length 946.7
  Top Layer w6: U7:A.2@883.5,1265.87 886.64,1269 934,1269 1215,1550 1315,1550 1378.38,1613.38 1504.17,1613.38 1545.79,1655 ; 1545,1655 1545.79,1655 ; U8:A.12@1662.34,1669.27 1624.27,1669.27 1615,1660 1550.79,1660 1545.79,1655
MID_TMS: U6:A.6 U8:A.6 | length 647.3
  Top Layer w6: U6:A.6@890,1535 975,1535 1186.05,1746.05 U8:A.6@1430.05,1746.05 U8:A.6@1449.88,1746.05
NetC4:A_2: C4:A.2 U1:A.4 | length 160.7
  Top Layer w10: U1:A.4@442.6,1763.98 442.6,1815.08 455.41,1827.9 506.87,1827.9 C4:A.2@535.2,1856.22
NetC13:A_1: C13:A.1 C14:A.2 L1:A.1 U2:A.4 | length 1219.1
  Top Layer w10: v2(-170,1265) -150.97,1245.97 9.2,1245.97 67.67,1304.45 67.67,1337.67 ; 65,1335 67.67,1337.67 ; v2(333.44,1630.72) 353.96,1610.2 353.96,1533.04 390,1497 390,1399.38 344.58,1353.97 156.03,1353.97 v2(150,1360) 90,1360 67.67,1337.67
  Bottom Layer w10: v2(-170,1265) -168.43,1266.57 C14:A.2@-168.43,1309.84 ; U2:A.4@137.64,1429.37 137.64,1379.36 150,1367 v2(150,1360) ; v2(333.44,1630.72) 333.44,1676.22 337.51,1680.29 L1:A.1@347.57,1680.29 348.43,1681.15 C13:A.1@470.54,1681.15
NetC15:A_1: C15:A.1 C16:A.2 L2:A.1 U2:A.9 | length 830.8
  Bottom Layer w10: C16:A.2@128.82,1549.84 128.82,1602.72 C15:A.1@116.69,1614.84 103.85,1627.68 103.85,1657.29 75.2,1685.95 L2:A.1@75.2,1694.84 75.2,1782.28 109.33,1816.42 219.93,1816.42 264.51,1771.83 264.51,1590.85 236.06,1562.4 U2:A.9@236.06,1429.37
NetC17:A_2: C17:A.2 U2:A.2 Y1:A.1 | length 578.7
  Top Layer w6: C17:A.2@-204.8,1368.46 v2@-204.8,1436.81 ; C17:A.2@-203.11,1377.01 -203.11,1437.07 v2(-203.82,1437.79) -182.41,1459.2 12.04,1459.2 v2(47.45,1423.78)
  Bottom Layer w6: Y1:A.1@-203.11,1377.01 v2@-203.11,1437.07 ; v2(47.45,1423.78) 47.45,1409.89 72.53,1384.82 89.38,1384.82 98.27,1393.7 U2:A.2@98.27,1429.37
NetC18:A_2: C18:A.2 U2:A.3 Y1:A.3 | length 383.2
  Bottom Layer w10: Y1:A.3@-116.5,1522.68 -115.04,1521.22 -54.22,1521.22 22,1445 22,1409.55 68.46,1363.09 110.36,1363.09 117.95,1370.68 U2:A.3@117.95,1429.37
NetC26_2: C26.2 U3.4 | length 71.4
  Top Layer w6: U3.4@2135,935 C26.2@2135,1006.38
NetC27_2: C27.2 R20.1 R23.1 U3.5 | length 241.3
  Top Layer w12: R20.1@1970,930 U3.5@2055,930 ; U3.5@2057.6,934.13 2089,965.54 v1(2089,967) 2089,991 2065,1015 C27.2@2065,1018.5
  Bottom Layer w12: R23.1@2071.38,930 2071.38,948.38 v1@2091,968 ; v1@2088,968 v1@2090,970
NetC28_1: C28.1 R24.1 | length 59
  Top Layer w12: R24.1@1641.72,1437.4 1641.72,1491.72 C28.1@1645,1495
NetC30_2: C30.2 R30.1 TP6.1 U4.6 | length 285.7
  Top Layer w6: C30.2@2205,1185 C30.2@2207.4,1187.4 ; C30.2@2206.72,1187.4 C30.2@2207.4,1187.4 ; U4.6@2210.5,1263.27 2210.5,1190.5 C30.2@2207.4,1187.4 ; TP6.1@2215,1095 2255,1135 v1(2255,1185) 2252.6,1187.4 C30.2@2207.4,1187.4
  Bottom Layer w6: R30.1@2206.72,1187.4 2252.6,1187.4 v1(2255,1185)
NetC60_2: C60.2 S8.4 U1.25 | length 717.2
  Top Layer w6: S8.4@818.1,227.4 867.4,227.4 890,250 v1(890,265) ; v1(1030,700) 1060,700 1073.97,713.97 U1.25@1073.97,728.34
  Mid-Layer 8 w6: v1(890,265) 912,287 912,367 959,414 959,638 1021,700 v1(1030,700)
  Bottom Layer w12: v1@1030,705 v1(1030,700) C60.2@1083.5,700
NetC61_2: C61.2 S8.3 U1.24 | length 841.1
  Top Layer w6: S8.3@818.1,177.4 869.4,177.4 907,215 v1(907,220) ; v1@1024,737 1035.03,748.03 U1.24@1073.97,748.03
  Mid-Layer 8 w6: v1@907,219 860,266 860,345 944,429 944,654 1024,734 v1(1024,738)
  Bottom Layer w12: v1(1024,738) 1051,765 C61.2@1083.5,765
NetD1_2: D1.2 R23.2 | length 172.5
  Top Layer w6: v1(2097,897) 2152,897 2161.06,906.06 D1.2@2223.1,906.06
  Bottom Layer w6: v1(2097,897) 2097,914 2113,930 R23.2@2115.62,930 R23.2@2116,930
NetD2:A_2: D2:A.2 R1:A.2 | length 132.5
  Top Layer w10: v2(315,1890) 360.68,1890 D2:A.2@364.09,1893.41 ; v2@319.93,1892.91 D2:A.2@357.85,1892.91
  Bottom Layer w10: v2(315,1890) 317.91,1892.91 R1:A.2@357.85,1892.91
NetD2_1: D2.1 U2.6 | length 91.5
  Top Layer w6: U2.6@2128.5,1655 D2.1@2128.5,1746.5
NetD2_2: D2.2 R10.2 | length 99.9
  Top Layer w6: v1(2116,1895) 2116.22,1894.78 D2.2@2116.22,1842.2
  Bottom Layer w6: v1(2116,1895) 2116.35,1894.65 R10.2@2116.34,1848.1
NetD3:A_1: D3:A.1 R7:A.2 | length 149.9
  Top Layer w12: v2(-230,975) -230,1020 D3:A.1@-205,1045
  Bottom Layer w12: v2(-230,975) -209.8,995.2 R7:A.2@-209.8,1036.22
NetD3_1: D3.1 U2.4 | length 83.3
  Top Layer w6: U2.4@2203.31,1655 D3.1@2203.31,1738.31
NetD3_2: D3.2 R11.2 | length 89.5
  Top Layer w6: v1(2215,1895) 2215.91,1894.09 D3.2@2215.91,1842.2
  Bottom Layer w6: R11.2@2215.08,1848.61 v1@2215.08,1884.92
NetD4:A_1: D4:A.1 R8:A.2 | length 153.6
  Top Layer w10: v2(-140,975) -140,1015 -116.79,1038.21 D4:A.1@-109.8,1031.22
  Bottom Layer w10: v2(-140,975) -136.24,975 -109.8,1001.43 R8:A.2@-109.8,1031.22
NetEC1_1: EC1.1 R1.2 | length 313.9
  Top Layer w10: R1.2@70.2,148.03 R1.2@71.06,147.17
  Top Layer w12: EC1.1@46.06,-150.67 46.06,-74.94 58,-63 58,59 75,76 R1.2@75,146.38 ; R1.2@70,146.38 R1.2@70,150
NetEC1_2: EC1.2 R2.1 | length 306.8
  Bottom Layer w10: R2.1@70.2,148.03 R2.1@71.06,147.17
  Bottom Layer w12: EC1.2@46.06,-150.67 46.06,41.06 70,65 R2.1@70,145
NetEC1_89: EC1.89 R7.1 | length 1669
  Top Layer w6: EC1.89@1557.87,-150.67 1557.87,-67.13 v1(1560,-65)
  Mid-Layer 8 w6: v1(1560,-65) 1590,-95 1775.46,-95 1798,-72.46 1798,-72 1840,-30 1840,480 1872,512 1872,677.46 1935,740.46 1935,1085 v1(1959,1109)
  Bottom Layer w6: R7.1@1896.5,1080 1930,1080 v1(1959,1109)
NetJ1:A_2: J1:A.2 U2:A.7 U3:A.5 | length 444.4
  Top Layer w10: J1:A.2@49.86,1742.36 v2(126.72,1742.36) v2@126.99,1742.64
  Bottom Layer w10: v2(126.72,1742.36) 148.54,1742.36 155.67,1735.23 155.67,1724.53 176.86,1724.53 184.11,1717.28 184.11,1540.89 196.69,1528.31 U2:A.7@196.69,1429.37
NetJ1:A_3: J1:A.3 U2:A.8 U3:A.3 | length 518.3
  Top Layer w10: J1:A.3@49.86,1710.87 128.22,1710.87 153.93,1685.16 153.93,1643.7 175.99,1621.64 v2(234.99,1621.64)
  Bottom Layer w10: U3:A.3@214.72,1685.16 214.72,1641.91 v2(234.99,1621.64) 216.38,1603.02 U2:A.8@216.38,1429.37
NetJ1:A_6: J1:A.6 J1:A.7 J1:A.8 J1:A.9 R6:A.1 | length 817.5
  Top Layer w10: J1:A.7@49.86,1537.64 J1:A.9@-166.67,1537.64 -166.67,1649.29 v2(-165.99,1649.98) -166.67,1650.66 J1:A.8@-166.67,1884.09 J1:A.6@49.86,1884.09
  Bottom Layer w10: v2@-168.43,1652.42 R6:A.1@-168.43,1689.84
NetL3_1: L3.1 R21.1 | length 85.1
  Top Layer w12: 1454.37,1475 1490,1475 R21.1@1525,1440
NetR3:A_2: R3:A.2 U2:A.24 | length 550.5
  Top Layer w10: v2@401.66,1588.46 v2@403.34,1586.79 ; v2(410,1585) 400.96,1585 373.47,1557.5 373.47,1535.88 427,1482.34 427,1426.09 435.01,1418.09 v2(435.01,1388.3) v2@434.61,1387.9
  Bottom Layer w10: R3:A.2@370.2,1588.46 v2@401.66,1588.46 ; v2@434.61,1387.9 412.64,1387.9 359.33,1334.59 359.33,1260.3 398.92,1220.71 U2:A.24@444.72,1220.71
NetR4:A_1: R4:A.1 U2:A.28 | length 74.7
  Bottom Layer w10: U2:A.28@444.72,1141.97 R4:A.1@519.45,1141.97
NetR5:A_1: R5:A.1 U2:A.32 | length 75.2
  Bottom Layer w10: U2:A.32@444.72,1063.23 R5:A.1@519.96,1063.23
NetR7:A_1: R7:A.1 U2:A.54 | length 347.2
  Top Layer w10: v2(-215,1180) -215,1175.64 -208.75,1169.39 -85.22,1169.39 -65.01,1149.18 v2(-65.01,1135.64)
  Bottom Layer w10: R7:A.1@-209.8,1083.46 -209.8,1168.34 ; v2(-65.01,1135.64) -38.99,1161.65 U2:A.54@7.72,1161.65
NetR8:A_1: R8:A.1 U2:A.55 | length 199
  Bottom Layer w10: R8:A.1@-109.8,1078.46 -109.8,1144.84 -74.01,1180.64 7.02,1180.64 U2:A.55@7.72,1181.34
NetR9:A_2: R9:A.2 R10:A.1 U4:A.4 | length 129
  Top Layer w6: U4:A.4@112.18,1149.46 U4:A.4@116.36,1153.64 ; U4:A.4@115,1155 U4:A.4@116.36,1153.64 ; U4:A.4@117.74,1155.02 U4:A.4@116.36,1153.64 ; R9:A.2@120,1108.62 120,1150 116.53,1153.47 U4:A.4@116.36,1153.64
  Top Layer w10: R10:A.1@44.99,1155.02 U4:A.4@117.74,1155.02
NetR10:A_2: R10:A.2 U2:A.61 U4:A.3 | length 339.5
  Top Layer w10: R10:A.2@44.99,1202.26 115.74,1202.26 118.12,1204.64 v2(175.99,1204.64)
  Bottom Layer w10: U2:A.61@7.72,1299.45 52.67,1299.45 147.48,1204.64 v2(175.99,1204.64)
NetR11:A_2: R11:A.2 U2:A.14 | length 117.8
  Bottom Layer w10: R11:A.2@320.2,1541.22 320.2,1524.8 334.49,1510.51 U2:A.14@334.49,1429.37
NetR12:A_2: R12:A.2 U2:A.60 | length 122.6
  Top Layer w12: R12:A.2@-84.8,1326.22 -84.8,1307.8 -57,1280 v1(-55,1280)
  Bottom Layer w12: v1(-55,1280) -54.76,1279.76 U2:A.60@7.72,1279.76
NetR13:A_2: R13:A.2 U2:A.36 | length 126.9
  Top Layer w12: v1(305,930) 306.57,931.57 R13:A.2@306.57,989.84
  Bottom Layer w12: v1(305,930) 314.8,939.8 U2:A.36@314.8,992.36
NetR14:A_2: R14:A.2 U2:A.6 | length 110.3
  Bottom Layer w10: R14:A.2@128.82,1499.84 162.79,1499.84 177.01,1485.62 U2:A.6@177.01,1429.37
NetR15:A_1: R15:A.1 S1:A.1 U8:A.1 | length 549
  Top Layer w6: S1:A.1@1223.1,1612.4 1223.1,1658.1 1224,1657.2 v1(1224,1657) ; U8:A.1@1430.05,1874 1475,1874 1484,1865 v1(1485,1865)
  Mid-Layer 3 w6: v1(1224,1657) 1224,1689 1272,1737 1319,1737 1423,1841 1463,1841 v1@1486,1864
  Bottom Layer w6: R15:A.1@1222,1701 1224,1699 v1(1224,1657) ; v1@1223.1,1666.9 R15:A.1@1223.1,1698.78
NetR16:A_1: R16:A.1 S1:A.2 U8:A.19 | length 589.3
  Top Layer w6: S1:A.2@1273.1,1612.4 1273.1,1658.1 1274,1657.2 v1(1274,1657) ; v1(1611.82,1850) 1613.41,1848.41 U8:A.19@1662.34,1848.41
  Mid-Layer 3 w6: v1(1274,1657) 1274,1703 1293,1722 1353,1722 1462,1831 1595,1831 v1@1613,1849
  Bottom Layer w6: v1(1274,1657) 1274,1696.68 R16:A.1@1278.1,1700.78
NetR28_1: R28.1 R32.1 U1.73 | length 322.1
  Top Layer w6: U1.73@1673,1161.41 U1.73@1682.23,1161.41 1726.41,1161.41 1742,1177 1742,1181.6 1755,1194.6 1755,1275 1775,1295 R28.1@1890,1295
NetR29_1: R29.1 U4.1 | length 69
  Top Layer w6: U4.1@2210.5,1371.53 R29.1@2210.5,1440.5
NetR33_1: R33.1 S1.3 | length 115.7
  Top Layer w6: v1(1843,1552) 1843.1,1552.1 S1.3@1843.1,1612.4
  Bottom Layer w6: v1@1842,1554 1843.1,1555.1 R33.1@1843.1,1608.78
NetR34_2: R34.2 S1.4 | length 121.7
  Top Layer w6: S1.4@1893.1,1612.4 1893.1,1556.9 v1(1898,1552) 1898,1553 v1@1899,1554
  Bottom Layer w6: v1(1898,1552) 1898.1,1552.1 R34.2@1898.1,1608.78
NetR35_2: R35.2 S7.6 | length 98.6
  Top Layer w12: v1(783,411) v1@783,410.8 ; v1@785,408.8 v1@783,410.8 ; S7.6@788.1,362.4 788.1,401.9 783,407 v1@783,410.8
  Bottom Layer w12: R35.2@779.6,367.4 779.6,404.6 783,408 v1(783,411)
NetR48_2: R48.2 R55.2 U1.14 | length 220
  Top Layer w6: R48.2@944,891 949,896 v1(991,896) 991,892 v1@990,891 ; v1@991,897 1006,912 1006,936 1014.88,944.88 U1.14@1073.97,944.88
  Bottom Layer w6: R55.2@944,892 948,896 v1(991,896)
NetR50_2: R50.2 R56.2 U1.15 | length 259.1
  Top Layer w6: R50.2@944.6,817.4 974.4,817.4 v1@993,836 ; v1(993,835) v1@993,836 ; 1034,925 1023,914 1023,901 1008,886 1008,867 993,852 v1@993,836 ; 1034,925.19 U1.15@1073.97,925.19
  Bottom Layer w6: R56.2@946,818 R56.2@949,821 ; R56.2@948,822 961,835 v1(993,835)
  Bottom Layer w12: R56.2@940,820 R56.2@941,821
NetR51_2: R51.2 R57.2 U1.13 | length 181.9
  Top Layer w6: R51.2@944.6,967.4 992.6,967.4 v1(995,965) 995.44,964.56 U1.13@1073.97,964.56
  Bottom Layer w12: R57.2@944.6,967.4 992.6,967.4 v1(995,965)
NetR52_2: R52.2 R58.2 U1.32 | length 211
  Top Layer w6: R58.2@1175,540 1188.5,526.5 R52.2@1265,526.5 ; R52.2@1259.99,545.01 U1.32@1259.99,660.43
NetR54_2: R54.2 R59.2 U1.42 | length 203.7
  Top Layer w6: R59.2@1358.9,538.9 R54.2@1433.1,538.9 ; R54.2@1435,540 1456.84,561.84 U1.42@1456.84,660.43
NetS2_5: S2.5 S4.1 | length 487
  Top Layer w6: S4.1@1020.27,321.3 1023.97,325 v1(1073,325) ; v1(1416,250) 1418.4,252.4 S2.5@1470.93,252.4
  Mid-Layer 3 w6: v1(1073,325) 1115,283 1383,283 1413,253 v1@1420,253
NetS3_2: S3.2 S4.4 | length 737.1
  Top Layer w6: v1(1111,329) 1118.7,321.3 S4.4@1165.93,321.3 ; v1(1695,255) 1744,255 S3.2@1746.6,252.4 ; S3.2@1747,252 S3.2@1746.6,252.4 ; S3.2@1747.83,252.4 S3.2@1746.6,252.4
  Mid-Layer 3 w6: v1(1111,329) 1388.14,329 1412.54,304.6 1427.46,304.6 1427.86,305 1663,305 1695,273 v1@1695,256
NetU2:A_40: U2:A.40 U2:A.41 | length 118.3
  Bottom Layer w10: U2:A.41@216.38,992.36 216.38,1039.33 222.52,1045.47 229.18,1045.47 236.06,1038.59 U2:A.40@236.06,992.36
NetU2:A_62: U2:A.62 U4:A.2 | length 231
  Top Layer w10: U4:A.2@117.91,1254.84 164.2,1254.84 v2(164.99,1255.64)
  Bottom Layer w10: U2:A.62@7.72,1319.13 61.99,1319.13 125.49,1255.64 v2(164.99,1255.64)
NetU2:A_63: U2:A.63 U4:A.1 | length 227.2
  Top Layer w10: U4:A.1@117.91,1304.84 164.84,1304.84 v2(165,1305) v2@166,1306
  Bottom Layer w10: U2:A.63@7.72,1338.82 67.18,1338.82 ; 65,1341 67.18,1338.82 ; v2(165,1305) 101,1305 67.18,1338.82 ; v2@166,1306 v2@169,1303
SW_3V3: C18.1 C20.2 C21.2 R14.2 U1.80 | length 398.4
  Top Layer w10: U1.80@1535.58,1268.7 1535.58,1303.58 1556,1324 v1@1561,1324
  Top Layer w15: v1(1560,1325) 1589,1325 1590,1324 v1(1590,1325)
  Bottom Layer w10: C18.1@1543.62,1275 C18.1@1543.62,1280
  Bottom Layer w15: C18.1@1543.62,1280 1543.62,1308.62 v1(1560,1325) ; C20.2@1570,1375 1571.5,1376.5 C21.2@1571.5,1445 1649,1445 R14.2@1654,1450 ; C20.2@1575,1375 1560,1360 v1(1560,1325) ; v1(1590,1325) v1(1560,1325)
SW_GND: C18.2 C20.1 C21.1 C28.2 R15.2 U1.82 | length 318.8
  Top Layer w12: v1(1495,1325) 1495,1320 1496.21,1318.79 U1.82@1496.21,1268.7 ; v1(1540,1490) 1542.4,1492.4 C28.2@1594.48,1492.4
  Bottom Layer w12: v1(1495,1325) 1496.38,1323.62 C18.2@1496.38,1280
  Bottom Layer w15: R15.2@1415,1455 1425,1445 C21.1@1508.5,1445 ; v1(1495,1325) 1510,1340 C20.1@1510,1375 ; C21.1@1505,1450 C21.1@1510,1445
SW_GPIO-26: R5.1 S6.2 | length 443.5
  Top Layer w6: S6.2@1877.17,252.4 1928.4,252.4 v1(1929,253)
  Bottom Layer w6: v1(1929,253) 1929,277 1950,298 1950,430 1985,465 1985,560 2000,575 R5.1@2033.5,575 R5.1@2040,575
SW_GPIO-27: R6.1 S6.5 | length 342.9
  Top Layer w6: v1(1971,252) 1972.2,252 1972.6,252.4 S6.5@2022.83,252.4
  Bottom Layer w6: v1(1971,252) 1972,252 2000,280 2000,469 R6.1@2033,502 ; R6.1@2039.25,494.25 R6.1@2045,500 ; R6.1@2043.5,500 R6.1@2045,500 ; R6.1@2050,500 R6.1@2045,500
X2: C22.1 R16.1 Y1.1 | length 163.8
  Top Layer w12: Y1.1@1908.13,1027.83 1952.17,1027.83 1954,1026 v1(1954,1024)
  Bottom Layer w6: R16.1@1889.6,1007.4 1936.4,1007.4 v1@1954,1025 ; v1(1954,1024) 1989,1024 1990,1025 C22.1@1995,1020
pads on no net: EC1.4 EC1.32 EC1.37 EC1.39 EC1.40 EC1.41 EC1.42 EC1.43 EC1.44 EC1.66 EC1.88 EC1.90 EC1.91 EC1.92 EC1.93 EC1.94 EC1.95 EC1.96 EC1.104 EC1.106 EC1.108 EC1.110 EC1.113 EC1.114 EC1.115 EC1.116 EC1.117 EC1.118 EC1.119 FID1.1 FID2.1 FID3.1 FID4.1 FID5.1 FID6.1 J1:A.4 J1:A.ALIGN1 J1:A.ALIGN2 S7.8 S7.9 U1.48 U1.49 U2:A.21 U2:A.22 U2:A.23 U2:A.26 U2:A.27 U2:A.29 U2:A.30 U2:A.33 U2:A.34 U2:A.43 U2:A.44 U2:A.45 U2:A.46 U2:A.48 U2:A.52 U2:A.53 U2:A.57 U2:A.58 U2:A.59 U3:A.2 U4:A.7 U8:A.3 U8:A.5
